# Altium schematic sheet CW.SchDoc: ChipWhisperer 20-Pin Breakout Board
size A; Engineer: Joe Grand; Revision: A; SheetNumber: 1; SheetTotal: 1; PageSetup: Record=PageOptions¦CenterHorizontal=True¦CenterVertical=True¦PrintScale=0.70¦XCorrection=1.00¦YCorrection=1.00¦PrintKind=0¦BorderSize=5000000¦LeftOffset=0¦BottomOffset=0¦Orientation=2¦PaperLength=1000¦PaperWidth=1000¦Scale=100¦PaperSource=7¦PrintQuality=-4¦MediaType=1¦DitherType=10¦PrintScaleMode=1¦PaperKind=Letter
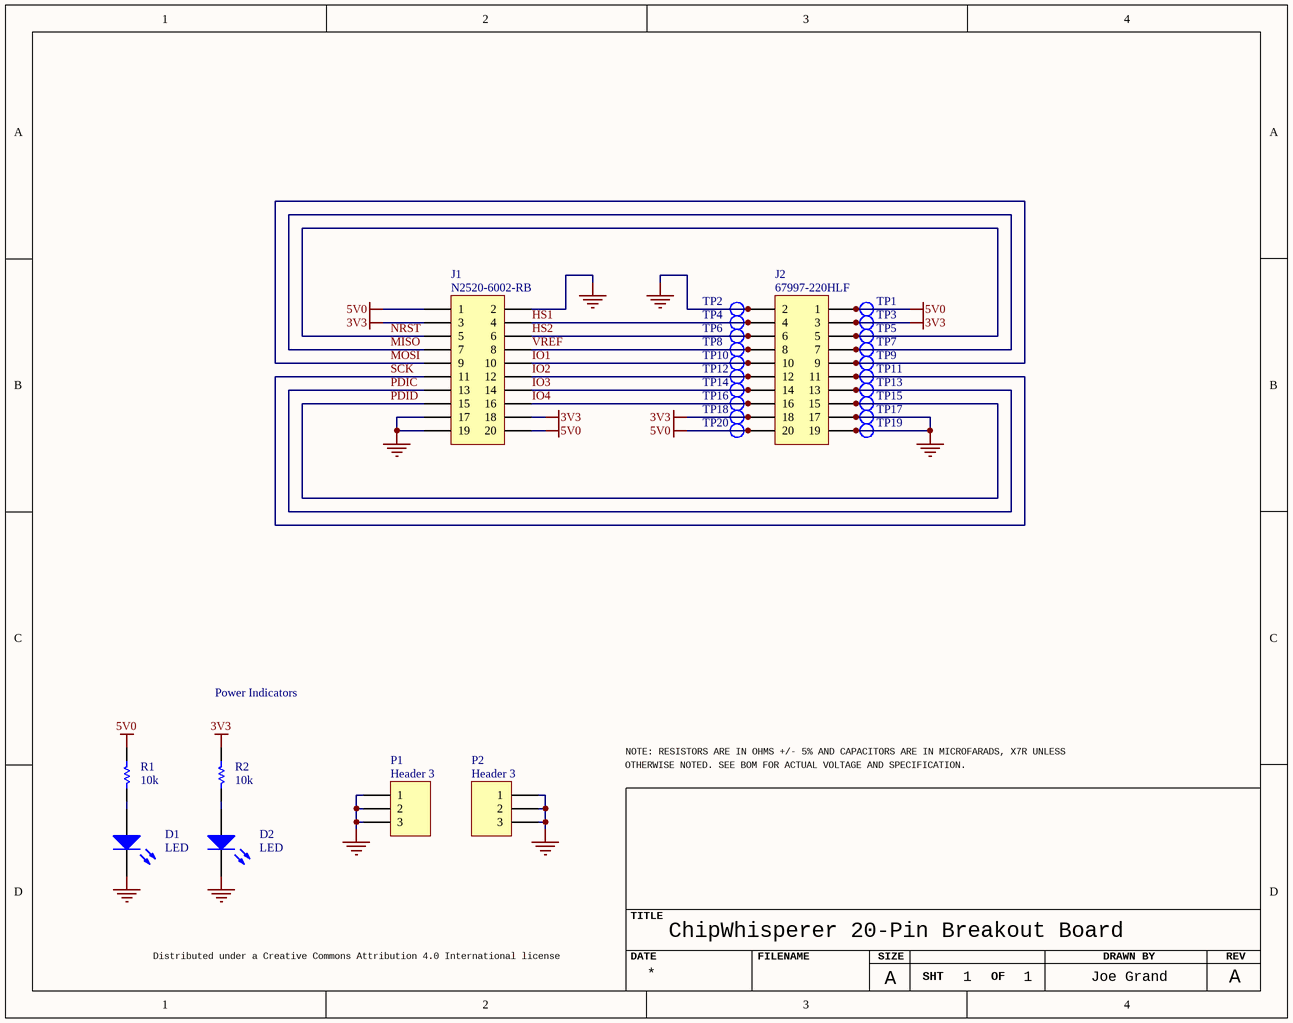
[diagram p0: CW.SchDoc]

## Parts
*  Page Size: A  Page Count: 1  OrgName: Joe Grand  Title: ChipWhisperer 20-Pin Breakout Board  (hidden comment: GIS Title Block)  (graphical)
D1  LED  [CC2012-0805 LED]
D2  LED  [CC2012-0805 LED]
J1  N2520-6002-RB  [HDR2X10 - SHROUD]
J2  67997-220HLF  [HDR2X10 - SHROUD]
P1  Header 3  [HEADER3]
P2  Header 3  [HEADER3]
R1  value 10k  [CC2012-0805]  (hidden comment: Res1)
R2  value 10k  [CC2012-0805]  (hidden comment: Res1)
TP1  TESTPOINT  [TESTPOINT - DOUBLE]  (value not drawn)
TP2  TESTPOINT  [TESTPOINT - DOUBLE]  (value not drawn)
TP3  TESTPOINT  [TESTPOINT - DOUBLE]  (value not drawn)
TP4  TESTPOINT  [TESTPOINT - DOUBLE]  (value not drawn)
TP5  TESTPOINT  [TESTPOINT - DOUBLE]  (value not drawn)
TP6  TESTPOINT  [TESTPOINT - DOUBLE]  (value not drawn)
TP7  TESTPOINT  [TESTPOINT - DOUBLE]  (value not drawn)
TP8  TESTPOINT  [TESTPOINT - DOUBLE]  (value not drawn)
TP9  TESTPOINT  [TESTPOINT - DOUBLE]  (value not drawn)
TP10  TESTPOINT  [TESTPOINT - DOUBLE]  (value not drawn)
TP11  TESTPOINT  [TESTPOINT - DOUBLE]  (value not drawn)
TP12  TESTPOINT  [TESTPOINT - DOUBLE]  (value not drawn)
TP13  TESTPOINT  [TESTPOINT - DOUBLE]  (value not drawn)
TP14  TESTPOINT  [TESTPOINT - DOUBLE]  (value not drawn)
TP15  TESTPOINT  [TESTPOINT - DOUBLE]  (value not drawn)
TP16  TESTPOINT  [TESTPOINT - DOUBLE]  (value not drawn)
TP17  TESTPOINT  [TESTPOINT - DOUBLE]  (value not drawn)
TP18  TESTPOINT  [TESTPOINT - DOUBLE]  (value not drawn)
TP19  TESTPOINT  [TESTPOINT - DOUBLE]  (value not drawn)
TP20  TESTPOINT  [TESTPOINT - DOUBLE]  (value not drawn)

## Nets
3V3: J1.3 J1.18 J2.3 J2.18 R2.1 TP3.1 TP18.1
5V0: J1.1 J1.20 J2.1 J2.20 R1.1 TP1.1 TP20.1
GND: D1.2(K) D2.2(K) J1.2 J1.17 J1.19 J2.2 J2.17 J2.19 P1.1 P1.2 P1.3 P2.1 P2.2 P2.3 TP2.1 TP17.1 TP19.1
HS1: J1.4 J2.4 TP4.1
HS2: J1.6 J2.6 TP6.1
IO1: J1.10 J2.10 TP10.1
IO2: J1.12 J2.12 TP12.1
IO3: J1.14 J2.14 TP14.1
IO4: J1.16 J2.16 TP16.1
MISO: J1.7 J2.7 TP7.1
MOSI: J1.9 J2.9 TP9.1
NRST: J1.5 J2.5 TP5.1
PDIC: J1.13 J2.13 TP13.1
PDID: J1.15 J2.15 TP15.1
SCK: J1.11 J2.11 TP11.1
VREF: J1.8 J2.8 TP8.1
NetD1_1: D1.1(A) R1.2
NetD2_1: D2.1(A) R2.2

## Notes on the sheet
- Power Indicators
- (near *) OTHERWISE NOTED. SEE BOM FOR ACTUAL VOLTAGE AND SPECIFICATION.
- (near *) NOTE: RESISTORS ARE IN OHMS +/- 5% AND CAPACITORS ARE IN MICROFARADS, X7R UNLESS
- Distributed under a Creative Commons Attribution 4.0 International license

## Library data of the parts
D1 D2 = LED0: Typical LED
J1 J2 = Header 10X2: Header, 10-Pin, Dual row
P1 P2 = Header 3: Header, 3-Pin
R1 R2 = Res1: Resistor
